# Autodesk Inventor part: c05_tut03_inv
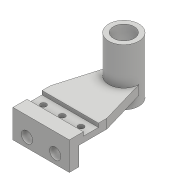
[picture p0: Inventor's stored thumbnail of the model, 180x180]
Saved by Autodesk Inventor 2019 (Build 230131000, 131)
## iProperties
Created: 2017-04
Part Number: c05_tut03_inv
Material: Generic
Document SubType Name: Modeling
Designer: CADCIM 00
Density: 1 g/cm^3
Appearance: Default
Author: CADCIM 00
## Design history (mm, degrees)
sketch "Sketch1"
  geometry: L1 (0, 0)-(-9, 0); L2 (-9, 0)-(-9, -4); L3 (-9, -4)-(-25, -4); L4 (-25, -4)-(-25, 0); L5 (-25, 0)-(-40, 0); L6 (-40, 0)-(-40, -30); L7 (-40, -30)-(-30, -30); L8 (-30, -30)-(-30, -10); L9 (-30, -10)-(0, -10); L10 (0, -10)-(0, 0)
  constraints: 20 end point, 7 perpendicular, 2 point on line, 1 horizontal, 1 vertical
  dimensions: "d0" = 4 distance of L1.end L2.end; "d1" = 16 distance of L2.end L3.end; "d3" = 15 distance of L4.end L5.end; "d4" = 30 distance of L5.end L6.end; "d5" = 10 distance of L6.end L7.end; "d6" = 10 distance of L9.end L1.start; "d7" = 40 distance between parallel lines of L10 L6
extrude "Extrusion1" new body sketch "Sketch1" stored distance "d8" = 60; taper "d9" = 0 deg
sketch "Sketch2"
  geometry: L1 (0, 9)-(60, 9) reference; L2 (0, 9)-(14, 57); L3 (14, 57)-(46, 57); L4 (46, 57)-(60, 9); L5 (60, 9)-(0, 9); L6 (30, 9)-(30, 57)
  constraints: 10 end point, 2 parallel, 1 midpoint, 1 vertical
  dimensions: "d10" = 48 distance between parallel lines of L3 L1; "d11" = 32 distance of L2.end L3.end
extrude "Extrusion2" join sketch "Sketch2" distance "d12" = 10; taper "d13" = 0 deg
workplane "Work Plane1"
sketch "Sketch3"
  geometry: L1 (46, 78)-(14, 78) reference; 2 further points
  constraints: 1 horizontal alignment, 1 midpoint, 2 other
extrude "Extrusion3" join sketch "Sketch3" distance "d15" = 60; taper "d16" = 0 deg
sketch "Sketch4"
  geometry: C1 r 11 at (0, 0); 1 further point
  constraints: 1 centre point
  dimensions: "d17" = 22 diameter of C1
extrude "Extrusion4" cut sketch "Sketch4" distance "d18" = 60; taper "d19" = 0 deg
sketch "Sketch5"
  geometry: L1 (0, 0)-(0, 16) reference; L2 (0, -15)-(60, -15) reference; C1 r 3 at (10, 7.5); C2 r 3 at (30, 7.5); C3 r 3 at (50, 7.5); 1 further point
  constraints: 3 centre point, 2 equal radius, 2 horizontal alignment
  dimensions: "d20" = 6 diameter of C1; "d21" = 10 distance from line of L1 C1.centre; "d22" = 20 distance of C1.centre C2.centre; "d24" = 22.5 distance from line of L2 C1.centre; "d33" = 20 distance of C3.centre C2.centre
extrude "Extrusion5" cut sketch "Sketch5" distance "d25" = 60; taper "d26" = 0 deg
sketch "Sketch6"
  geometry: L1 (0, 0)-(0, 30) reference; L2 (0, 0)-(60, 0) reference; C1 r 6 at (15, 10); C2 r 6 at (45, 10); 1 further point
  constraints: 2 centre point, 1 equal radius, 1 horizontal alignment
  dimensions: "d27" = 15 distance from line of L1 C1.centre; "d28" = 12 diameter of C1; "d29" = 30 distance of C2.centre C1.centre; "d30" = 10 distance from line of L2 C1.centre
extrude "Extrusion6" cut sketch "Sketch6" stored distance "d31" = 60; taper "d32" = 0 deg
body "Solid1"
